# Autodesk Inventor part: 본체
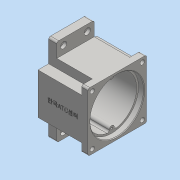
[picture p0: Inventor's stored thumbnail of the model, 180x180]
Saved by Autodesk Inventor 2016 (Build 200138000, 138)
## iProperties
Created: 2020-08
Part Number: 본체
Material: 일반
Document SubType Name: Modeling
Designer: User
Density: 1 g/cm^3
Appearance: 기본값
Author: User
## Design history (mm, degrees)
sketch "스케치1"
  geometry: L1 (30, 70)-(-30, 70); L2 (-30, 70)-(-30, -70); L3 (-30, -70)-(30, -70); L4 (30, -70)-(30, 70); L5 (30, 70)-(-30, -70); L6 (-30, 70)-(30, -70); L7 (47, 33)-(-47, 33); L8 (-47, 33)-(-47, -33); L9 (-47, -33)-(47, -33); L10 (47, -33)-(47, 33); L11 (47, 33)-(-47, -33); L12 (-47, 33)-(47, -33); 1 further point
  constraints: 24 end point, 4 midpoint, 4 parallel, 2 horizontal, 2 perpendicular
  dimensions: "d2" = 140 distance between parallel lines of L3 L1; "d3" = 60 distance between parallel lines of L2 L4; "d4" = 66 distance of L9.end L7.start; "d5" = 94 distance between parallel lines of L8 L10
extrude "돌출1" new body sketch "스케치1" distance "d6" = 13; taper "d7" = 0 deg
sketch "스케치3"
  geometry: L1 (-47, 47)-(47, 47); L2 (47, 47)-(47, -47); L3 (47, -47)-(-47, -47); L4 (-47, -47)-(-47, 47); L5 (-47, 47)-(47, -47); L6 (47, 47)-(-47, -47); 1 further point
  constraints: 12 end point, 2 midpoint, 2 parallel, 1 horizontal, 1 perpendicular
  dimensions: "d8" = 94 distance of L2.end L3.end; "d9" = 94 distance of L1.end L2.end
extrude "돌출2" join sketch "스케치3" distance "d10" = 67; taper "d11" = 0 deg
sketch "스케치4"
  geometry: L1 (33, -30)-(33, -47) reference; L2 (33, -47)-(47, -47) reference; L3 (47, -47)-(47, -30) reference; L4 (47, -30)-(33, -30) reference; L5 (-33, -47)-(-33, -30) reference; L6 (-33, -30)-(-47, -30) reference; L7 (-47, -30)-(-47, -47) reference; L8 (-47, -47)-(-33, -47) reference; L9 (-47, 30)-(-33, 30) reference; L10 (-33, 30)-(-33, 47) reference; L11 (-33, 47)-(-47, 47) reference; L12 (-47, 47)-(-47, 30) reference; L13 (33, 30)-(47, 30) reference; L14 (47, 30)-(47, 47) reference; L15 (47, 47)-(33, 47) reference; L16 (33, 47)-(33, 30) reference; 1 further point
extrude "돌출3" cut sketch "스케치4" distance "d12" = 57; taper "d13" = 0 deg
sketch "스케치5"
  geometry: C1 r 27.5 at (0, -11); 1 further point
  constraints: 1 centre point, 1 vertical alignment
  dimensions: "d14" = 55 diameter of C1; "d15" = 11 distance of point (0, 0) C1.centre
extrude "돌출4" join sketch "스케치5" distance "d16" = 7; taper "d17" = 0 deg
sketch "스케치6"
  geometry: C1 r 16 at (0, 0); C2 r 27.5 at (0, 0) reference; 1 further point
  constraints: 1 centre point, 1 concentric
  dimensions: "d18" = 16 radius of C1
extrude "돌출5" cut sketch "스케치6" distance "d19" = 8.3; taper "d20" = 0 deg
sketch "스케치7"
  geometry: C1 r 43 at (0, 0); 1 further point
  constraints: 1 centre point, 1 coincident
  dimensions: "d21" = 43 radius of C1
extrude "돌출6" cut sketch "스케치7" distance "d22" = 9; taper "d23" = 0 deg
sketch "스케치8"
  geometry: C1 r 40 at (0, 0); 1 further point
  constraints: 1 centre point, 1 coincident
  dimensions: "d24" = 80 diameter of C1
extrude "돌출7" cut sketch "스케치8" distance "d25" = 62; taper "d26" = 0 deg
sketch "스케치9"
  geometry: C1 r 21 at (0, -11); C2 r 15 at (0, 20); 1 further point
  constraints: 2 centre point, 2 vertical alignment
  dimensions: "d27" = 42 diameter of C1; "d28" = 30 diameter of C2; "d29" = 11 distance of point (0, 0) C1.centre; "d30" = 20 distance of C2.centre point (0, 0)
extrude "돌출8" join sketch "스케치9" distance "d31" = 7; taper "d32" = 0 deg
sketch "스케치10"
  geometry: C1 r 17.5 at (0, -11); A1 r 21 centre (0, -11) between (-8.978, 7.984) and (8.978, 7.984) reference; 1 further point
  constraints: 1 centre point, 1 concentric
  dimensions: "d33" = 35 diameter of C1
extrude "돌출9" cut sketch "스케치10" distance "d34" = 10; taper "d35" = 0 deg
sketch "스케치11"
  geometry: C1 r 12.5 at (0, 0); C2 r 17.5 at (0, 0) reference; 1 further point
  constraints: 1 centre point, 1 concentric
  dimensions: "d36" = 12.5 radius of C1
extrude "돌출10" cut sketch "스케치11" distance "d37" = 15; taper "d38" = 0 deg
sketch "스케치12"
  geometry: C1 r 11 at (0, 20); A1 r 15 centre (0, 20) between (8.978, 7.984) and (-8.978, 7.984) reference; 1 further point
  constraints: 1 centre point, 1 concentric
  dimensions: "d39" = 22 diameter of C1
extrude "돌출11" cut sketch "스케치12" distance "d40" = 7; taper "d41" = 0 deg
sketch "스케치13"
  geometry: C1 r 9.5 at (0, 0); C2 r 11 at (0, 0) reference; 1 further point
  constraints: 1 centre point, 1 concentric
  dimensions: "d42" = 19 diameter of C1
extrude "돌출12" cut sketch "스케치13" distance "d43" = 3; taper "d44" = 0 deg
sketch "스케치14"
  geometry: C1 r 40 at (0, 0) reference; A1 r 4 centre (-36, 0) between (-36.19, -3.995) and (-36.19, 3.995); A2 r 3 centre (-36.333, -6.992) between (-36.19, -3.995) and (-39.279, -7.559); A3 r 3 centre (-36.333, 6.992) between (-39.279, 7.559) and (-36.19, 3.995); A4 r 40 centre (0, 0) between (-39.279, -7.559) and (-39.279, 7.559) reference; 1 further point
  constraints: 8 point on circle, 5 tangent, 3 centre point, 2 horizontal alignment
  dimensions: "d45" = 8 diameter of A1; "d46" = 36 distance of A1.centre point (0, 0); "d47" = 6 diameter of A2; "d48" = 6 diameter of A3
extrude "돌출13" join sketch "스케치14" stored distance "d49" = 3; taper "d50" = 0 deg
sketch "스케치16"
  geometry: C1 r 4 at (-36, 0); A1 r 4 centre (-36, 0) between (-36.19, -3.995) and (-36.19, 3.995) reference; 1 further point
  constraints: 1 centre point, 1 coincident
  dimensions: "d51" = 4 radius of C1
hole "구멍1" sketch "스케치16" at (-36, 0) diameter "d52" = 3.242; stored, may be unused: countersink angle "d56" = 90 deg, drill point angle "d58" = 118 deg; dims "d53" = 7, "d54" = 4, "d55" = 2, "d57" = 9
sketch "스케치17"
  geometry: L1 (47, -47)-(33, -47) reference; C1 r 3.5 at (40, -40); 1 further point
  constraints: 1 centre point
  dimensions: "d60" = 40 horizontal distance of point (0, 0) C1.centre; "d61" = 40 horizontal distance of point (0, 0) C1.centre; "d62" = 7 diameter of C1
extrude "돌출14" cut sketch "스케치17" distance "d63" = 10; taper "d64" = 0 deg
sketch "스케치18"
  geometry: 2 further points
  dimensions: "d71" = 60 horizontal distance of point (0, 0) point (-60, 19); "d72" = 19 vertical distance of point (0, 0) point (-60, 19)
hole "구멍2" sketch "스케치18" at (-60, 19) diameter "d73" = 4.5; stored, may be unused: countersink angle "d77" = 90 deg, drill point angle "d79" = 118 deg; dims "d74" = 7, "d75" = 10, "d76" = 5, "d78" = 15
sketch "스케치19"
  geometry: L1 (0, 66)-(0, 0) reference; 3 further points
  constraints: 1 horizontal alignment, 1 midpoint, 1 other
  dimensions: "d86" = 40 distance of point (40, 33) point (0, 33)
feature "엠보싱1" sketch "스케치19" dims "d2" = 140, "d3" = 60, "d87" = 0.5, "d88" = 0
chamfer "모따기1" distance "d89" = 1; stored, may be unused: second distance "d90" = 2, angle "d91" = 45 deg
chamfer "모따기2" distance "d92" = 0.8; stored, may be unused: second distance "d93" = 2, angle "d94" = 30 deg
fillet "모깎기1" dims "d95" = 3
fillet "모깎기2" dims "d96" = 3
chamfer "모따기3" distance "d97" = 1; stored, may be unused: second distance "d98" = 2, angle "d99" = 45 deg
fillet "모깎기3" dims "d100" = 3
node "솔리드1"
mirror "대칭1"
pattern_linear "직사각형 패턴1" dims "d67" = 80
pattern_linear "직사각형 패턴2" dims "d82" = 38
node "투영된 루프1"
node "투영된 루프2"
node "투영된 루프3"
node "투영된 루프4"
